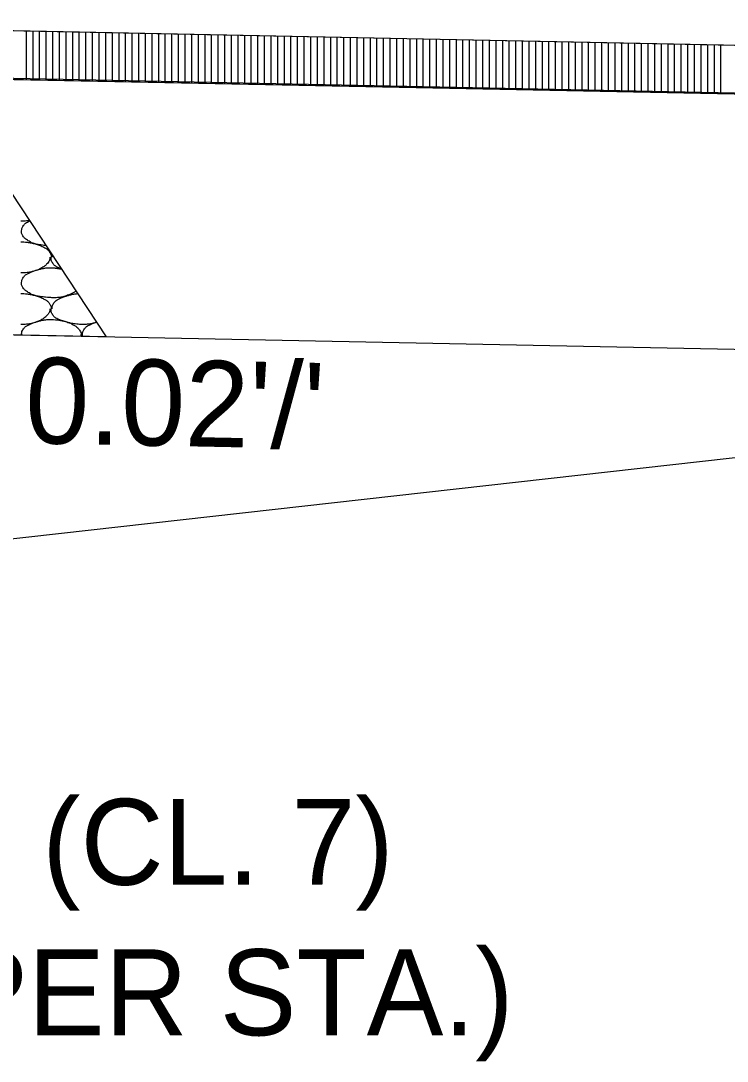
# Model space of a CAD drawing. Extents: x 1373719 to 1374161, y 379835 to 380167.
# Drawn here: x 1373969.11 to 1373974.45, y 379968.75 to 379976.62 of the extents above; entities that cross this region are included whole.
import ezdxf

# ---------------------------------------------------------------- set-up
doc = ezdxf.new("R2010")
doc.units = 0
for name, color, linetype in [('ACHM Surface', 7, 'Continuous'), ('Aggregate Base Course', 7, 'Continuous'), ('GREEN_TXT', 7, 'Continuous'), ('Pavement Layers', 7, 'Continuous'), ('SIGNATURE', 7, 'Continuous'), ('T_Drafting', 7, 'Continuous')]:
    doc.layers.add(name, color=color, linetype=linetype)

msp = doc.modelspace()

# ---------------------------------------------------------------- linework, layer by layer
for p, q in [((1373965.3548, 379976.6186), (1373981.8548, 379976.2886)), ((1373965.3548, 379974.3183), (1373992.0048, 379973.7853))]:
    msp.add_line(p, q)
at = {"layer": 'ACHM Surface'}
for p, q in [((1373969.1555, 379976.1726), (1373969.1555, 379976.5426)), ((1373969.2055, 379976.1716), (1373969.2055, 379976.5416)), ((1373969.2555, 379976.1706), (1373969.2555, 379976.5406)), ((1373969.3055, 379976.1696), (1373969.3055, 379976.5396)), ((1373969.3555, 379976.1686), (1373969.3555, 379976.5386)), ((1373969.4055, 379976.1676), (1373969.4055, 379976.5376)), ((1373969.4555, 379976.1666), (1373969.4555, 379976.5366)), ((1373969.5055, 379976.1656), (1373969.5055, 379976.5356)), ((1373969.5555, 379976.1646), (1373969.5555, 379976.5346)), ((1373969.6055, 379976.1636), (1373969.6055, 379976.5336)), ((1373969.6555, 379976.1626), (1373969.6555, 379976.5326)), ((1373969.7055, 379976.1616), (1373969.7055, 379976.5316)), ((1373969.7555, 379976.1606), (1373969.7555, 379976.5306)), ((1373969.8055, 379976.1596), (1373969.8055, 379976.5296)), ((1373969.8555, 379976.1586), (1373969.8555, 379976.5286)), ((1373969.9055, 379976.1576), (1373969.9055, 379976.5276)), ((1373969.9555, 379976.1566), (1373969.9555, 379976.5266)), ((1373970.0055, 379976.1556), (1373970.0055, 379976.5256)), ((1373970.0555, 379976.1546), (1373970.0555, 379976.5246)), ((1373970.1055, 379976.1536), (1373970.1055, 379976.5236)), ((1373970.1555, 379976.1526), (1373970.1555, 379976.5226)), ((1373970.2055, 379976.1516), (1373970.2055, 379976.5216)), ((1373970.2555, 379976.1506), (1373970.2555, 379976.5206)), ((1373970.3055, 379976.1496), (1373970.3055, 379976.5196)), ((1373970.3555, 379976.1486), (1373970.3555, 379976.5186)), ((1373970.4055, 379976.1476), (1373970.4055, 379976.5176)), ((1373970.4555, 379976.1466), (1373970.4555, 379976.5166)), ((1373970.5055, 379976.1456), (1373970.5055, 379976.5156)), ((1373970.5555, 379976.1446), (1373970.5555, 379976.5146)), ((1373970.6055, 379976.1436), (1373970.6055, 379976.5136)), ((1373970.6555, 379976.1426), (1373970.6555, 379976.5126)), ((1373970.7055, 379976.1416), (1373970.7055, 379976.5116)), ((1373970.7555, 379976.1406), (1373970.7555, 379976.5106)), ((1373970.8055, 379976.1396), (1373970.8055, 379976.5096)), ((1373970.8555, 379976.1386), (1373970.8555, 379976.5086)), ((1373970.9055, 379976.1376), (1373970.9055, 379976.5076)), ((1373970.9555, 379976.1366), (1373970.9555, 379976.5066)), ((1373971.0055, 379976.1356), (1373971.0055, 379976.5056)), ((1373971.0555, 379976.1346), (1373971.0555, 379976.5046)), ((1373971.1055, 379976.1336), (1373971.1055, 379976.5036)), ((1373971.1555, 379976.1326), (1373971.1555, 379976.5026)), ((1373971.2055, 379976.1316), (1373971.2055, 379976.5016)), ((1373971.2555, 379976.1306), (1373971.2555, 379976.5006)), ((1373971.3055, 379976.1296), (1373971.3055, 379976.4996)), ((1373971.3555, 379976.1286), (1373971.3555, 379976.4986)), ((1373971.4055, 379976.1276), (1373971.4055, 379976.4976)), ((1373971.4555, 379976.1266), (1373971.4555, 379976.4966)), ((1373971.5055, 379976.1256), (1373971.5055, 379976.4956)), ((1373971.5555, 379976.1246), (1373971.5555, 379976.4946)), ((1373971.6055, 379976.1236), (1373971.6055, 379976.4936)), ((1373971.6555, 379976.1226), (1373971.6555, 379976.4926)), ((1373971.7055, 379976.1216), (1373971.7055, 379976.4916)), ((1373971.7555, 379976.1206), (1373971.7555, 379976.4906)), ((1373971.8055, 379976.1196), (1373971.8055, 379976.4896)), ((1373971.8555, 379976.1186), (1373971.8555, 379976.4886)), ((1373971.9055, 379976.1176), (1373971.9055, 379976.4876)), ((1373971.9555, 379976.1166), (1373971.9555, 379976.4866)), ((1373972.0055, 379976.1156), (1373972.0055, 379976.4856)), ((1373972.0555, 379976.1146), (1373972.0555, 379976.4846)), ((1373972.1055, 379976.1136), (1373972.1055, 379976.4836)), ((1373972.1555, 379976.1126), (1373972.1555, 379976.4826)), ((1373972.2055, 379976.1116), (1373972.2055, 379976.4816)), ((1373972.2555, 379976.1106), (1373972.2555, 379976.4806)), ((1373972.3055, 379976.1096), (1373972.3055, 379976.4796)), ((1373972.3555, 379976.1086), (1373972.3555, 379976.4786)), ((1373972.4055, 379976.1076), (1373972.4055, 379976.4776)), ((1373972.4555, 379976.1066), (1373972.4555, 379976.4766)), ((1373972.5055, 379976.1056), (1373972.5055, 379976.4756)), ((1373972.5555, 379976.1046), (1373972.5555, 379976.4746)), ((1373972.6055, 379976.1036), (1373972.6055, 379976.4736)), ((1373972.6555, 379976.1026), (1373972.6555, 379976.4726)), ((1373972.7055, 379976.1016), (1373972.7055, 379976.4716)), ((1373972.7555, 379976.1006), (1373972.7555, 379976.4706)), ((1373972.8055, 379976.0996), (1373972.8055, 379976.4696)), ((1373972.8555, 379976.0986), (1373972.8555, 379976.4686)), ((1373972.9055, 379976.0976), (1373972.9055, 379976.4676)), ((1373972.9555, 379976.0966), (1373972.9555, 379976.4666)), ((1373973.0055, 379976.0956), (1373973.0055, 379976.4656)), ((1373973.0555, 379976.0946), (1373973.0555, 379976.4646)), ((1373973.1055, 379976.0936), (1373973.1055, 379976.4636)), ((1373973.1555, 379976.0926), (1373973.1555, 379976.4626)), ((1373973.2055, 379976.0916), (1373973.2055, 379976.4616)), ((1373973.2555, 379976.0906), (1373973.2555, 379976.4606)), ((1373973.3055, 379976.0896), (1373973.3055, 379976.4596)), ((1373973.3555, 379976.0886), (1373973.3555, 379976.4586)), ((1373973.4055, 379976.0876), (1373973.4055, 379976.4576)), ((1373973.4555, 379976.0866), (1373973.4555, 379976.4566)), ((1373973.5055, 379976.0856), (1373973.5055, 379976.4556)), ((1373973.5555, 379976.0846), (1373973.5555, 379976.4546)), ((1373973.6055, 379976.0836), (1373973.6055, 379976.4536)), ((1373973.6555, 379976.0826), (1373973.6555, 379976.4526)), ((1373973.7055, 379976.0816), (1373973.7055, 379976.4516)), ((1373973.7555, 379976.0806), (1373973.7555, 379976.4506)), ((1373973.8055, 379976.0796), (1373973.8055, 379976.4496)), ((1373973.8555, 379976.0786), (1373973.8555, 379976.4486)), ((1373973.9055, 379976.0776), (1373973.9055, 379976.4476)), ((1373973.9555, 379976.0766), (1373973.9555, 379976.4466)), ((1373974.0055, 379976.0756), (1373974.0055, 379976.4456)), ((1373974.0555, 379976.0746), (1373974.0555, 379976.4446)), ((1373974.1055, 379976.0736), (1373974.1055, 379976.4436)), ((1373974.1555, 379976.0726), (1373974.1555, 379976.4426)), ((1373974.2055, 379976.0716), (1373974.2055, 379976.4416)), ((1373974.2555, 379976.0706), (1373974.2555, 379976.4406)), ((1373974.3055, 379976.0696), (1373974.3055, 379976.4396)), ((1373974.3555, 379976.0686), (1373974.3555, 379976.4386)), ((1373974.4055, 379976.0676), (1373974.4055, 379976.4376))]:
    msp.add_line(p, q, dxfattribs=at)
at = {"layer": 'Aggregate Base Course'}
for points, degree in [([(1373969.1778, 379975.1088), (1373969.1677, 379975.1069), (1373969.1576, 379975.1056), (1373969.136, 379975.1047), (1373969.1245, 379975.1047), (1373969.1132, 379975.1052)], 3), ([(1373969.3029, 379974.9196), (1373969.2967, 379974.9202), (1373969.2904, 379974.9209), (1373969.2624, 379974.924), (1373969.2409, 379974.9274), (1373969.2017, 379974.9365), (1373969.1865, 379974.9459), (1373969.1529, 379974.967), (1373969.1384, 379974.9779), (1373969.1193, 379975.0071), (1373969.118, 379975.0177), (1373969.1194, 379975.0424), (1373969.1225, 379975.0571), (1373969.1436, 379975.0851), (1373969.1551, 379975.0926), (1373969.1727, 379975.1017), (1373969.1763, 379975.1036), (1373969.18, 379975.1054)], 3), ([(1373969.1132, 379974.9468), (1373969.115, 379974.9467), (1373969.1168, 379974.9469), (1373969.1186, 379974.9468)], 2), ([(1373969.1186, 379974.9468), (1373969.1449, 379974.9471), (1373969.1714, 379974.9432), (1373969.1978, 379974.9378), (1373969.23, 379974.9312), (1373969.2597, 379974.9214), (1373969.2896, 379974.9054), (1373969.3095, 379974.8947), (1373969.3254, 379974.8808), (1373969.3364, 379974.8604), (1373969.3411, 379974.8516), (1373969.3428, 379974.8427), (1373969.3436, 379974.8334), (1373969.3436, 379974.8328), (1373969.3437, 379974.8322), (1373969.3436, 379974.8316)], 3), ([(1373969.3328, 379974.8316), (1373969.3328, 379974.8298), (1373969.3328, 379974.828), (1373969.3328, 379974.8262), (1373969.3321, 379974.8079), (1373969.3205, 379974.7921), (1373969.3076, 379974.7776), (1373969.2994, 379974.7684), (1373969.2908, 379974.7618), (1373969.2806, 379974.756), (1373969.2624, 379974.7457), (1373969.2445, 379974.737), (1373969.2248, 379974.7308), (1373969.1992, 379974.7227), (1373969.1737, 379974.7156), (1373969.1474, 379974.7146), (1373969.136, 379974.7141), (1373969.1245, 379974.7141), (1373969.1132, 379974.7146)], 3), ([(1373969.4186, 379974.7446), (1373969.4104, 379974.7475), (1373969.4022, 379974.7507), (1373969.3749, 379974.7624), (1373969.359, 379974.7762), (1373969.3438, 379974.8056), (1373969.3418, 379974.8157), (1373969.3418, 379974.828), (1373969.3418, 379974.8298), (1373969.3418, 379974.8316)], 3), ([(1373969.349, 379974.8316), (1373969.349, 379974.8322), (1373969.3489, 379974.8328), (1373969.3491, 379974.8382), (1373969.3496, 379974.843), (1373969.3505, 379974.8476)], 3), ([(1373969.5301, 379974.5761), (1373969.5258, 379974.5727), (1373969.5213, 379974.5698), (1373969.4982, 379974.5567), (1373969.4803, 379974.548), (1373969.435, 379974.5337), (1373969.4095, 379974.5272), (1373969.37, 379974.5248), (1373969.3567, 379974.5247), (1373969.3237, 379974.5269), (1373969.304, 379974.5288), (1373969.2624, 379974.5334), (1373969.2409, 379974.5368), (1373969.2017, 379974.5459), (1373969.1865, 379974.5553), (1373969.1529, 379974.5764), (1373969.1384, 379974.5873), (1373969.1193, 379974.6165), (1373969.118, 379974.6271), (1373969.1194, 379974.6518), (1373969.1225, 379974.6665), (1373969.1436, 379974.6945), (1373969.1551, 379974.702), (1373969.1808, 379974.7154), (1373969.1924, 379974.7212), (1373969.2228, 379974.7314), (1373969.2407, 379974.7368), (1373969.2703, 379974.7445), (1373969.2816, 379974.747), (1373969.3098, 379974.7514), (1373969.3269, 379974.752), (1373969.3436, 379974.7506)], 3), ([(1373969.3436, 379974.7506), (1373969.3691, 379974.7509), (1373969.3948, 379974.7472), (1373969.4203, 379974.7421)], 2), ([(1373969.1132, 379974.5562), (1373969.115, 379974.5561), (1373969.1168, 379974.5563), (1373969.1186, 379974.5562)], 2), ([(1373969.1186, 379974.5562), (1373969.1449, 379974.5565), (1373969.1714, 379974.5526), (1373969.1978, 379974.5472), (1373969.23, 379974.5406), (1373969.2597, 379974.5308), (1373969.2896, 379974.5148), (1373969.3095, 379974.5041), (1373969.3254, 379974.4902), (1373969.3364, 379974.4698), (1373969.3411, 379974.461), (1373969.3428, 379974.4521), (1373969.3436, 379974.4428), (1373969.3436, 379974.4422), (1373969.3437, 379974.4416), (1373969.3436, 379974.441)], 3), ([(1373969.349, 379974.441), (1373969.349, 379974.4416), (1373969.3489, 379974.4422), (1373969.3493, 379974.458), (1373969.3536, 379974.4725), (1373969.3733, 379974.4996), (1373969.3855, 379974.5076), (1373969.4112, 379974.521), (1373969.4228, 379974.5268), (1373969.4532, 379974.537), (1373969.4711, 379974.5424), (1373969.5007, 379974.5501), (1373969.512, 379974.5526), (1373969.53, 379974.5554), (1373969.5365, 379974.5561), (1373969.5431, 379974.5565)], 3), ([(1373969.3328, 379974.441), (1373969.3328, 379974.4392), (1373969.3328, 379974.4374), (1373969.3321, 379974.4173), (1373969.3205, 379974.4015), (1373969.2994, 379974.3778), (1373969.2908, 379974.3712), (1373969.2624, 379974.3551), (1373969.2445, 379974.3464), (1373969.1992, 379974.3321), (1373969.1737, 379974.325), (1373969.136, 379974.3235), (1373969.1245, 379974.3235), (1373969.1132, 379974.324)], 3), ([(1373969.574, 379974.324), (1373969.5716, 379974.324), (1373969.5692, 379974.324), (1373969.5469, 379974.324), (1373969.5271, 379974.3258), (1373969.4863, 379974.3332), (1373969.4663, 379974.3396), (1373969.4282, 379974.3505), (1373969.4111, 379974.3562), (1373969.3749, 379974.3718), (1373969.359, 379974.3856), (1373969.3438, 379974.415), (1373969.3418, 379974.4251), (1373969.3418, 379974.4374), (1373969.3418, 379974.4392), (1373969.3418, 379974.441)], 3), ([(1373969.1184, 379974.243), (1373969.1185, 379974.2442), (1373969.1185, 379974.2454), (1373969.1194, 379974.2612), (1373969.1225, 379974.2759), (1373969.1436, 379974.3039), (1373969.1551, 379974.3114), (1373969.1808, 379974.3248), (1373969.1924, 379974.3306), (1373969.2228, 379974.3408), (1373969.2407, 379974.3462), (1373969.2703, 379974.3539), (1373969.2816, 379974.3564), (1373969.3098, 379974.3608), (1373969.3269, 379974.3614), (1373969.3436, 379974.36)], 3), ([(1373969.3436, 379974.36), (1373969.3699, 379974.3603), (1373969.3964, 379974.3564), (1373969.455, 379974.3444), (1373969.4847, 379974.3346), (1373969.5345, 379974.3079), (1373969.5481, 379974.2934), (1373969.5671, 379974.265), (1373969.5701, 379974.2552), (1373969.5678, 379974.2424), (1373969.5667, 379974.2382), (1373969.5653, 379974.2341)], 3), ([(1373969.686, 379974.3403), (1373969.6859, 379974.3403), (1373969.6857, 379974.3402), (1373969.66, 379974.3321), (1373969.6345, 379974.325), (1373969.5968, 379974.3235), (1373969.5853, 379974.3235), (1373969.574, 379974.324)], 3), ([(1373969.5799, 379974.2338), (1373969.5792, 379974.2381), (1373969.5791, 379974.2424), (1373969.5802, 379974.2612), (1373969.5833, 379974.2759), (1373969.6044, 379974.3039), (1373969.6159, 379974.3114), (1373969.6416, 379974.3248), (1373969.6532, 379974.3306), (1373969.6723, 379974.337), (1373969.6789, 379974.3391), (1373969.6855, 379974.3412)], 3)]:
    msp.add_open_spline(points, degree=degree, dxfattribs=at)
at = {"layer": 'Pavement Layers'}
msp.add_line((1373965.3548, 379976.2486), (1373981.8524, 379975.9186), dxfattribs=at)
at = {"layer": 'SIGNATURE'}
msp.add_line((1373965.3548, 379976.258), (1373981.8524, 379975.9281), dxfattribs=at)
for points in [[(1373945.8548, 379975.7985), (1373946.2404, 379976.184), (1373948.8548, 379976.2886), (1373965.3548, 379976.6186), (1373981.8548, 379976.2886), (1373984.4692, 379976.184), (1373984.8548, 379975.7985), (1373981.8473, 379975.9188), (1373965.3548, 379976.2486), (1373948.8623, 379975.9188)], [(1373961.0836, 379974.2329), (1373962.7242, 379976.2054), (1373965.3548, 379976.2486), (1373968.4651, 379976.1864), (1373969.7589, 379974.2302), (1373965.3548, 379974.3183)]]:
    msp.add_lwpolyline(points, close=True, dxfattribs=at)
at = {"layer": 'T_Drafting'}
msp.add_lwpolyline([(1373907.3475, 379968.9245), (1373923.8936, 379968.8482), (1373942.8103, 379971.015), (1373964.3039, 379972.1704), (1373992.0776, 379975.2912), (1374006.816, 379975.489), (1374019.9843, 379975.489)], dxfattribs=at)

# ---------------------------------------------------------------- texts
at = {"layer": 'GREEN_TXT'}
msp.add_text("0.02'/'", height=0.65, rotation=358.854, dxfattribs=at).set_placement((1373969.1411, 379973.4269))
for s, p in [('20\'-0" AGGREGATE BASE CRSE. (CL. 7)', (1373955.6138, 379970.0873)), ('10" COMP\'D DEPTH (129.75 TONS PER STA.)', (1373954.3957, 379968.9498))]:
    msp.add_text(s, height=0.65, dxfattribs=at).set_placement(p)

doc.saveas('drawing.dxf')
